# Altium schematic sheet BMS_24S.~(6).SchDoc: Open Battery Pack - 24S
size A4; Author: Morgane Vallée; Revision: 1.0; SheetNumber: 3; SheetTotal: 5
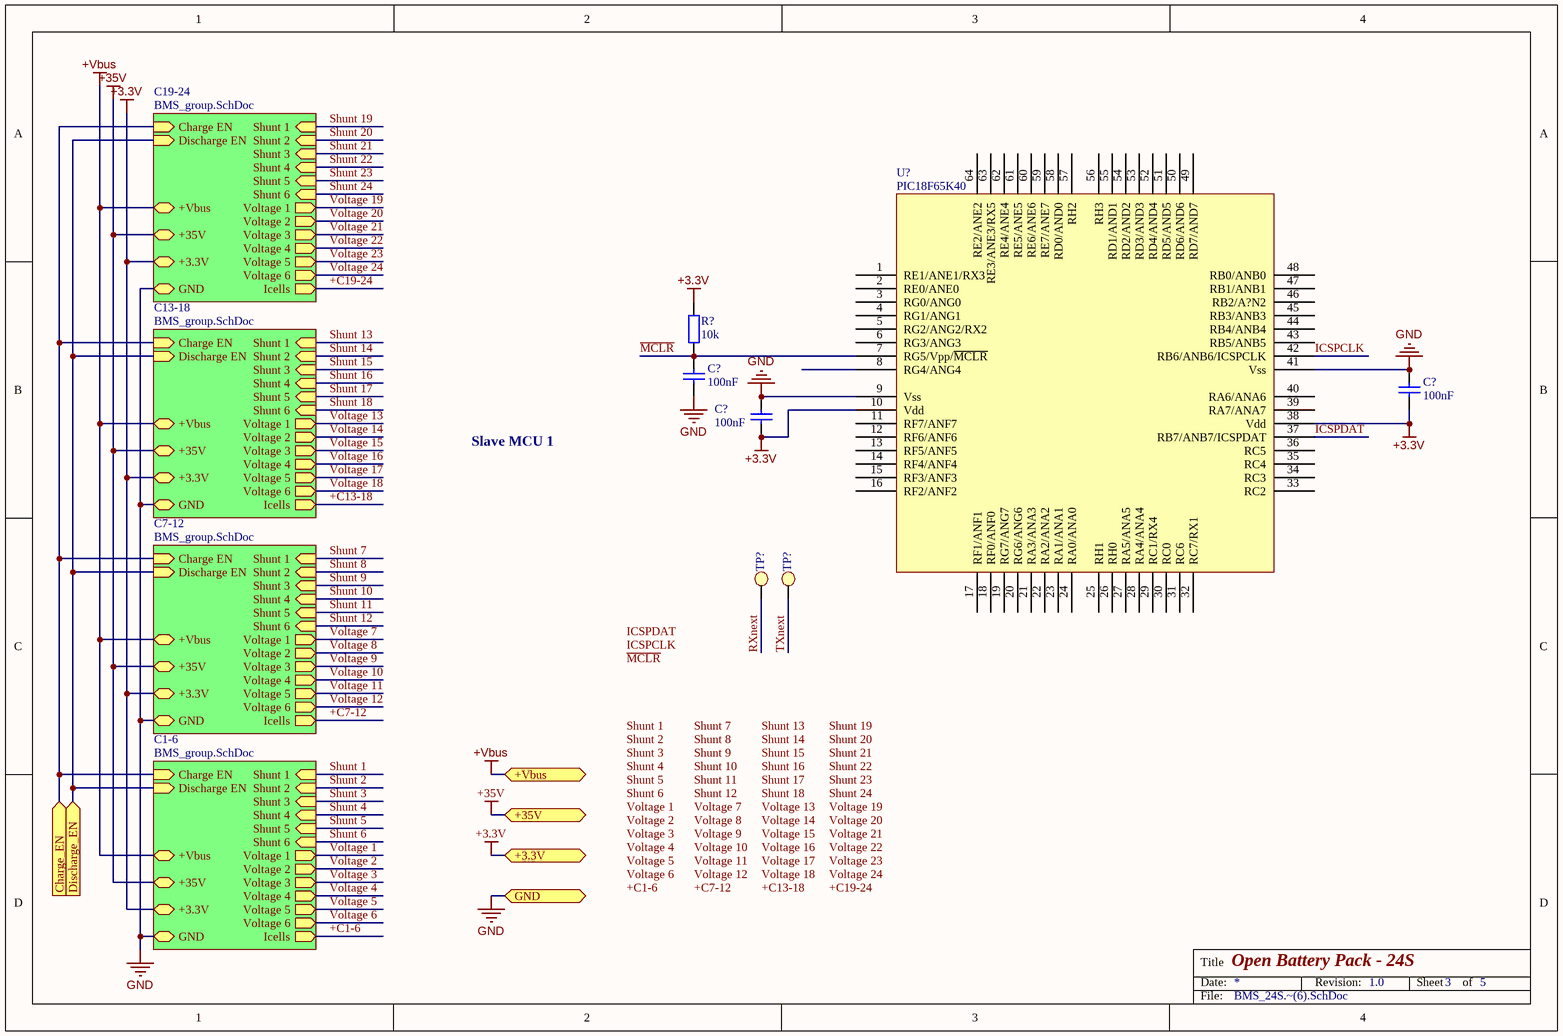
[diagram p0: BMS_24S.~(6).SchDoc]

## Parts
(Parts that share a designator on the sheet are numbered #1, #2 ... from top to bottom, then left to right.)
C?#1  100nF  [C0603]
C?#2  100nF  [C0603]
C?#3  100nF  [C0603]
R?  10k  [R0603]
TP?#1  Test Point  [Test Point]  (value not drawn)
TP?#2  Test Point  [Test Point]  (value not drawn)
U?  PIC18F65K40  [LQFP64]

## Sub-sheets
C1-6 = BMS_group.SchDoc: +Vbus, Shunt 1 (in), Shunt 2 (in), Shunt 3 (in), Shunt 4 (in), Shunt 5 (in), Shunt 6 (in), Voltage 1 (out), Voltage 2 (out), Voltage 3 (out), Voltage 4 (out), +3.3V, Voltage 5 (out), Voltage 6 (out), Charge EN (in), Discharge EN (in), Icells (out), GND, +35V
C7-12 = BMS_group.SchDoc: +Vbus, Shunt 1 (in), Shunt 2 (in), Shunt 3 (in), Shunt 4 (in), Shunt 5 (in), Shunt 6 (in), Voltage 1 (out), Voltage 2 (out), Voltage 3 (out), Voltage 4 (out), +3.3V, Voltage 5 (out), Voltage 6 (out), Charge EN (in), Discharge EN (in), Icells (out), GND, +35V
C13-18 = BMS_group.SchDoc: +Vbus, Shunt 1 (in), Shunt 2 (in), Shunt 3 (in), Shunt 4 (in), Shunt 5 (in), Shunt 6 (in), Voltage 1 (out), Voltage 2 (out), Voltage 3 (out), Voltage 4 (out), +3.3V, Voltage 5 (out), Voltage 6 (out), Charge EN (in), Discharge EN (in), Icells (out), GND, +35V
C19-24 = BMS_group.SchDoc: +Vbus, Shunt 1 (in), Shunt 2 (in), Shunt 3 (in), Shunt 4 (in), Shunt 5 (in), Shunt 6 (in), Voltage 1 (out), Voltage 2 (out), Voltage 3 (out), Voltage 4 (out), +3.3V, Voltage 5 (out), Voltage 6 (out), Charge EN (in), Discharge EN (in), Icells (out), GND, +35V

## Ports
+3.3V, +35V, +Vbus, Charge_EN (in), Discharge_EN (in), GND

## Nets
+3.3V: C?#2.2 C?#3.2 R?.2 U?.10(Vdd) U?.38(Vdd) ; port +3.3V, sheet C1-6/+3.3V, sheet C7-12/+3.3V, sheet C13-18/+3.3V, sheet C19-24/+3.3V
+35V: port +35V, sheet C1-6/+35V, sheet C7-12/+35V, sheet C13-18/+35V, sheet C19-24/+35V
+Vbus: port +Vbus, sheet C1-6/+Vbus, sheet C7-12/+Vbus, sheet C13-18/+Vbus, sheet C19-24/+Vbus
GND: C?#1.1 C?#2.1 C?#3.1 U?.9(Vss) U?.41(Vss) ; port GND, sheet C1-6/GND, sheet C7-12/GND, sheet C13-18/GND, sheet C19-24/GND
Charge_EN: port Charge_EN, sheet C1-6/Charge EN, sheet C7-12/Charge EN, sheet C13-18/Charge EN, sheet C19-24/Charge EN
Discharge_EN: port Discharge_EN, sheet C1-6/Discharge EN, sheet C7-12/Discharge EN, sheet C13-18/Discharge EN, sheet C19-24/Discharge EN
ICSPCLK: U?.42(RB6/ANB6/ICSPCLK)
ICSPDAT: U?.37(RB7/ANB7/ICSPDAT)
~{MCLR}: C?#1.2 R?.1 U?.7(RG5/Vpp/~{MCLR})
RXnext: TP?#1.1
TXnext: TP?#2.1

Not connected (* = marked no-connect by the designer): U? 1(RE1/ANE1/RX3) 2(RE0/ANE0) 3(RG0/ANG0) 4(RG1/ANG1) 5(RG2/ANG2/RX2) 6(RG3/ANG3) 8(RG4/ANG4) 11(RF7/ANF7) 12(RF6/ANF6) 13(RF5/ANF5) 14(RF4/ANF4) 15(RF3/ANF3) 16(RF2/ANF2) 17(RF1/ANF1) 18(RF0/ANF0) 19(RG7/ANG7) 20(RG6/ANG6) 21(RA3/ANA3) 22(RA2/ANA2) 23(RA1/ANA1) 24(RA0/ANA0) 25(RH1) 26(RH0) 27(RA5/ANA5) 28(RA4/ANA4) 29(RC1/RX4) 30(RC0) 31(RC6) 32(RC7/RX1) 33(RC2) 34(RC3) 35(RC4) 36(RC5) 39(RA7/ANA7) 40(RA6/ANA6) 43(RB5/ANB5) 44(RB4/ANB4) 45(RB3/ANB3) 46(RB2/A?N2) 47(RB1/ANB1) 48(RB0/ANB0) 49(RD7/AND7) 50(RD6/AND6) 51(RD5/AND5) 52(RD4/AND4) 53(RD3/AND3) 54(RD2/AND2) 55(RD1/AND1) 56(RH3) 57(RH2) 58(RD0/AND0) 59(RE7/ANE7) 60(RE6/ANE6) 61(RE5/ANE5) 62(RE4/ANE4) 63(RE3/ANE3/RX5) 64(RE2/ANE2)

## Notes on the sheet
- Slave MCU 1
- Labels drawn without touching a wire or pin: +C1-6, +C7-12, +C13-18, +C19-24, ICSPCLK, ICSPDAT, Shunt 1, Shunt 2, Shunt 3, Shunt 4, Shunt 5, Shunt 6, Shunt 7, Shunt 8, Shunt 9, Shunt 10, Shunt 11, Shunt 12, Shunt 13, Shunt 14, Shunt 15, Shunt 16, Shunt 17, Shunt 18, Shunt 19, Shunt 20, Shunt 21, Shunt 22, Shunt 23, Shunt 24, Voltage 1, Voltage 2, Voltage 3, Voltage 4, Voltage 5, Voltage 6, Voltage 7, Voltage 8, Voltage 9, Voltage 10, Voltage 11, Voltage 12, Voltage 13, Voltage 14, Voltage 15, Voltage 16, Voltage 17, Voltage 18, Voltage 19, Voltage 20, Voltage 21, Voltage 22, Voltage 23, Voltage 24, ~{MCLR}

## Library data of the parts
C?#1-C?#3 = Cap: Capacitor
R? = Res2: Resistor
U? = PIC18F65K40: 64-Pin, Low-Power, High-Performance Microcontrollers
